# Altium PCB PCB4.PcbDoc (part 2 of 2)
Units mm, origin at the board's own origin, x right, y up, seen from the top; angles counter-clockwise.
Board outline 70 x 70 mm, 2 copper layers (Top Layer, Bottom Layer); 41 components, 63 nets, 218 pads, 36 vias.
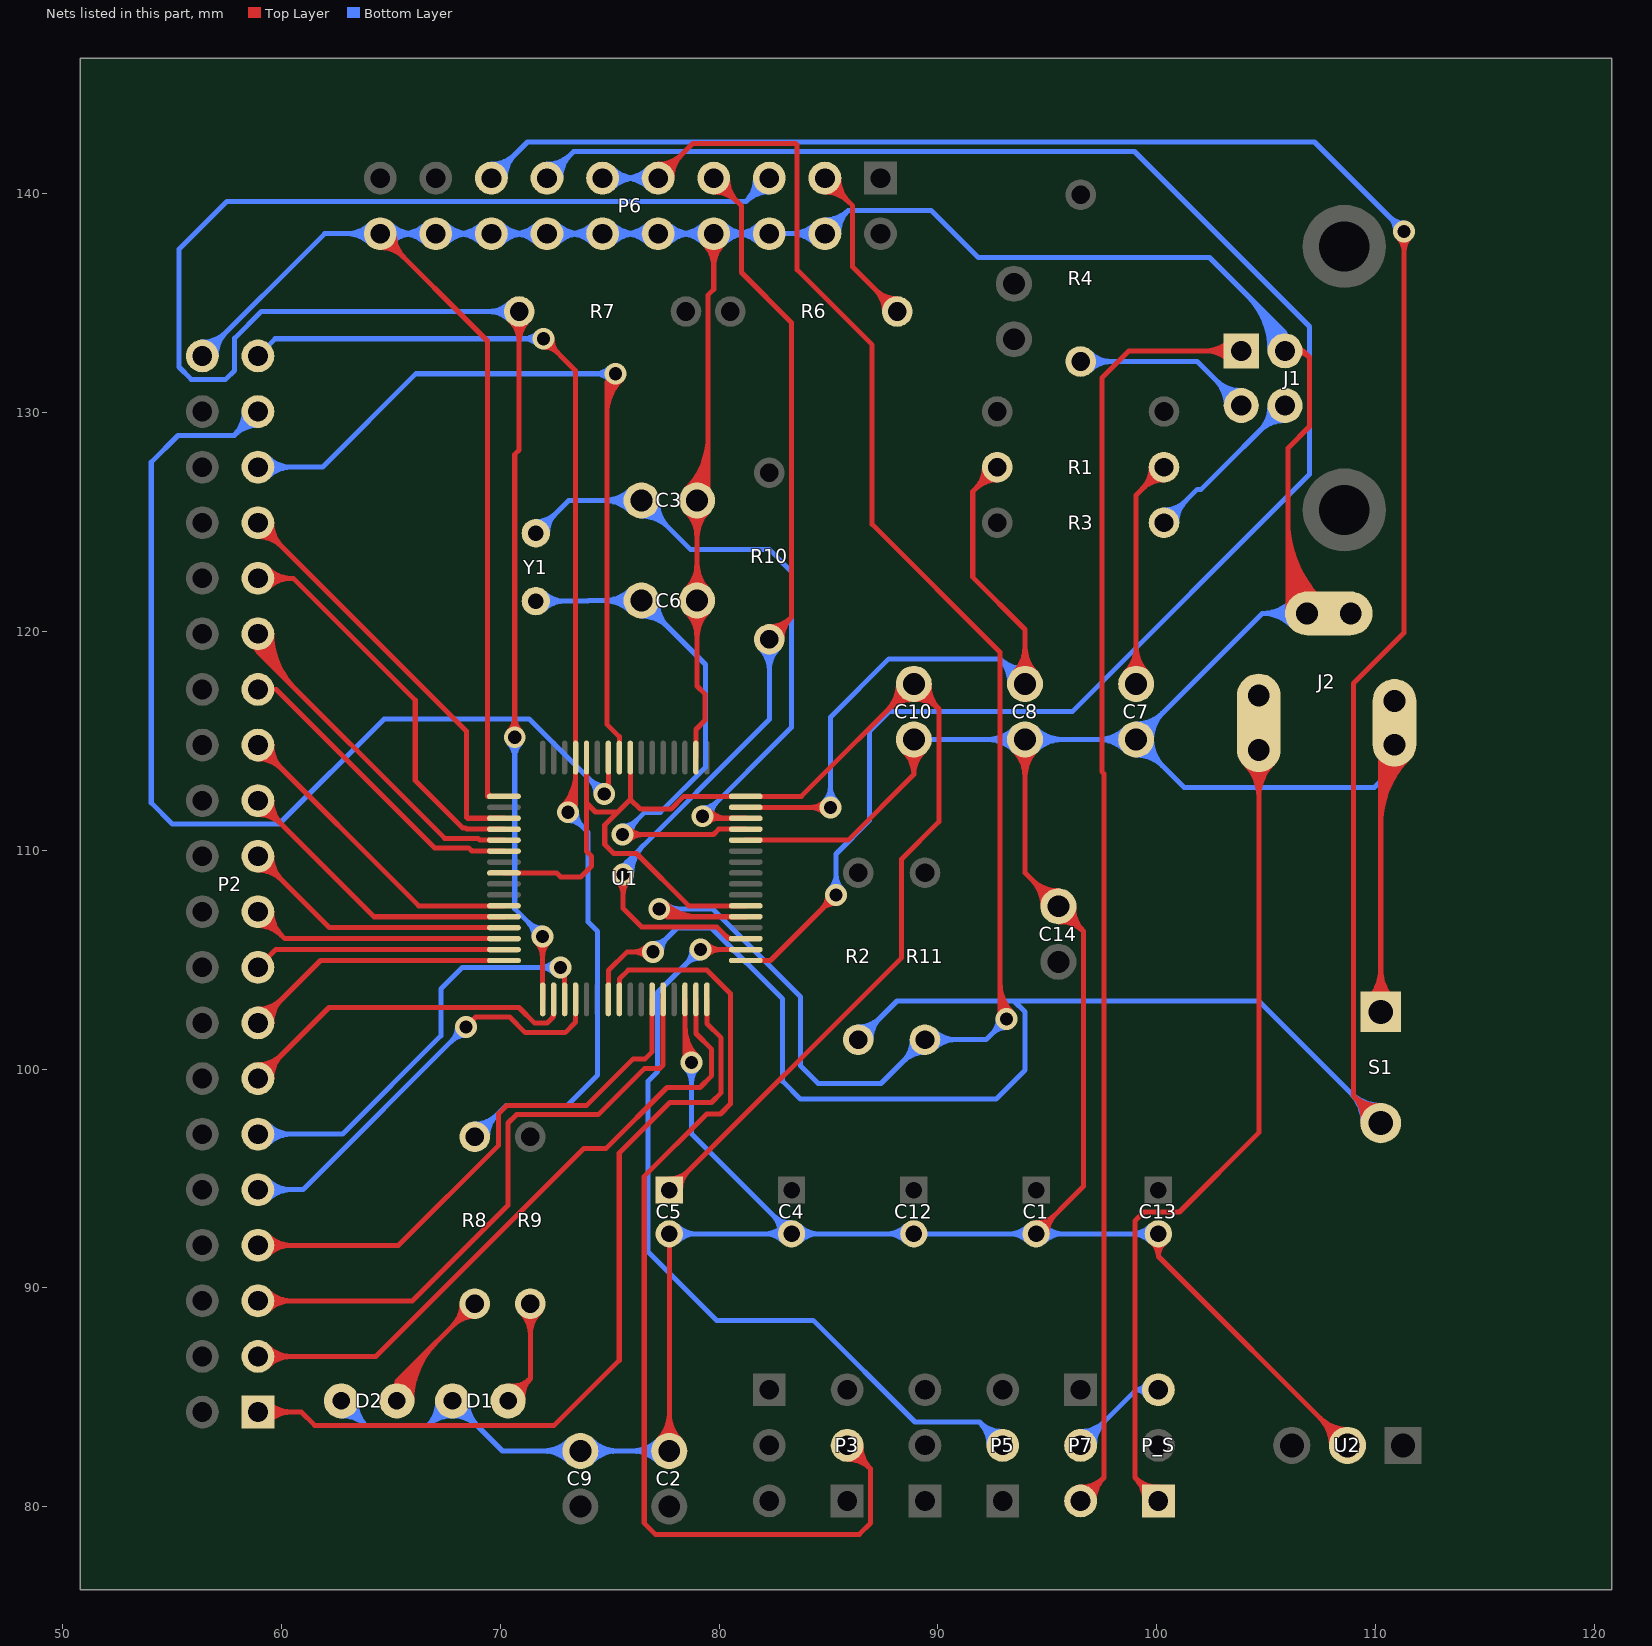
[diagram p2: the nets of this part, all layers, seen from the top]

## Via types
v1: diameter 1, hole 0.6, Top Layer to Bottom Layer, 36 vias

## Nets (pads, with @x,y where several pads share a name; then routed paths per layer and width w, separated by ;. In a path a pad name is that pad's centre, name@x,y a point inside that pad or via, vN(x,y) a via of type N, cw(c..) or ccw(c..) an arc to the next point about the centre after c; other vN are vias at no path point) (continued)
GND: C1.2 C2.1 C3.2 C4.2 C5.2 C6.2 C7.2 C8.2 C9.1 C10.1 C12.2 C13.2 C14.1 D1.2 D2.2 J1.4 J2.2 J2.2A J2.2B J2.3 J2.3A J2.3B P2.40 P6.4 P6.6 P6.8 P6.10 P6.12 P6.14 P6.16 P6.18 P6.20 S1.1 U1.2 U1.17 U1.46 U1.60 U2.2 | length 565.4
  Top Layer w0.23: P6.20@64.516,137.541 cw(c64.516,136.008) 65.6,137.092 cw(c66.684,138.176) P6.20@65.151,138.176 ; P6.20@64.516,137.771 cw(c64.516,136.793) 65.207,137.485 cw(c65.899,138.176) P6.20@64.921,138.176 ; P6.20@64.516,138.176 69.418,133.274 69.418,112.462 U1.17@70.167,112.462 ; 69.418,112.726 ccw(c69.781,112.726) U1.17@69.524,112.469 ; C2.1@77.222,83.052 ccw(c76.01,84.264) 77.724,84.264 ccw(c79.438,84.264) C2.1@78.226,83.052 ; C2.1@77.385,82.889 ccw(c76.565,83.709) 77.724,83.709 ccw(c78.883,83.709) C2.1@78.063,82.889 ; C2.1@77.724,82.55 C5.2@77.724,92.472 ; 78.442,100.843 ccw(c79.278,100.843) v1@78.687,100.252 ; 78.442,101.398 ccw(c79.834,101.398) v1@78.85,100.414 ; 78.442,101.953 ccw(c80.389,101.953) v1@79.012,100.577 ; U1.46@78.442,103.187 78.442,100.603 v1(78.74,100.305) ; C6.2@78.492,120.91 cw(c77.28,119.698) 78.994,119.698 cw(c80.708,119.698) C6.2@79.496,120.91 ; C6.2@78.492,121.914 ccw(c77.28,123.126) 78.994,123.126 ccw(c80.708,123.126) C6.2@79.496,121.914 ; C3.2@78.492,125.482 cw(c77.28,124.27) 78.994,124.27 cw(c80.708,124.27) C3.2@79.496,125.482 ; C3.2@78.492,126.486 ccw(c76.053,128.925) 79.502,128.925 ; C6.2@78.655,121.073 cw(c77.835,120.253) 78.994,120.253 cw(c80.153,120.253) C6.2@79.333,121.073 ; C6.2@78.655,121.751 ccw(c77.835,122.571) 78.994,122.571 ccw(c80.153,122.571) C6.2@79.333,121.751 ; C3.2@78.655,125.645 cw(c77.835,124.825) 78.994,124.825 cw(c80.153,124.825) C3.2@79.333,125.645 ; C3.2@78.655,126.323 ccw(c76.609,128.369) 79.502,128.369 ; C3.2@78.817,126.161 ccw(c77.164,127.814) 79.502,127.814 ; U1.2@78.942,114.237 78.942,115.517 79.352,115.927 79.352,117.147 78.994,117.505 C6.2@78.994,121.412 C3.2@78.994,125.984 79.502,125.984 79.502,135.382 79.756,135.636 P6.8@79.756,138.176 ; C3.2@78.98,125.998 ccw(c77.719,127.259) 79.502,127.259 ; C3.2@79.142,125.836 ccw(c78.275,126.703) 79.502,126.703 ; P6.8@79.307,137.727 cw(c78.223,136.643) 79.756,136.643 cw(c81.289,136.643) P6.8@80.205,137.727 ; P6.8@79.47,137.89 cw(c78.778,137.198) 79.756,137.198 cw(c80.734,137.198) P6.8@80.042,137.89 ; U1.60@81.217,110.462 85.9,110.462 88.9,113.462 ; C10.1@88.424,114.536 cw(c87.452,113.462) 88.9,113.462 ; C10.1@88.578,114.706 cw(c87.921,113.98) 88.9,113.98 cw(c89.879,113.98) C10.1@89.222,114.706 ; C10.1@88.9,115.062 88.9,113.462 ; C10.1@89.376,114.536 ccw(c90.348,113.462) 88.9,113.462 ; C8.2@93.478,114.56 cw(c92.266,113.348) 93.98,113.348 cw(c95.694,113.348) C8.2@94.482,114.56 ; C8.2@93.641,114.723 cw(c92.821,113.903) 93.98,113.903 cw(c95.139,113.903) C8.2@94.319,114.723 ; C8.2@93.98,115.062 93.98,108.966 C14.1@95.504,107.442 96.647,106.299 ; C1.2@94.488,92.472 96.647,94.631 96.647,106.299 ; C1.2@94.488,92.752 ccw(c94.488,93.428) 94.966,92.95 ccw(c95.444,92.472) C1.2@94.768,92.472 ; C1.2@94.488,92.982 ccw(c94.488,94.213) 95.359,93.343 ccw(c96.229,92.472) C1.2@94.998,92.472 ; C14.1@94.794,107.442 ccw(c93.08,107.442) 94.292,108.654 ccw(c95.504,109.866) C14.1@95.504,108.152 ; C14.1@95.024,107.442 ccw(c93.865,107.442) 94.685,108.261 ccw(c95.504,109.081) C14.1@95.504,107.922 ; C14.1@95.524,106.962 cw(c95.567,105.959) 96.277,106.669 cw(c96.987,107.379) C14.1@95.984,107.422 ; C14.1@95.534,106.733 cw(c95.597,105.249) 96.647,106.299 ; C14.1@96.213,107.412 ccw(c97.697,107.349) 96.647,106.299 ; C13.2@99.766,92.067 cw(c99.287,91.44) 100.076,91.44 ; C13.2@100.076,92.472 100.076,91.44 ; C13.2@100.386,92.067 ccw(c100.865,91.44) 100.076,91.44 ; J1.4@105.859,132.826 cw(c106.254,132.195) 106.781,132.721 ; J1.4@105.862,132.822 106.68,132.822 106.985,132.517 ; J1.4@105.981,132.631 cw(c106.411,131.943) 106.985,132.517 ; 105.994,121.729 ccw(c107.769,121.729) J2.3@106.514,120.474 ; 105.994,122.284 ccw(c108.324,122.284) J2.3@106.677,120.637 ; 105.994,122.839 ccw(c108.879,122.839) J2.3@106.839,120.799 ; 105.994,123.395 ccw(c109.435,123.395) J2.3@107.002,120.962 ; 105.994,123.95 ccw(c109.99,123.95) J2.3@107.165,121.125 ; 105.994,124.505 ccw(c110.545,124.505) J2.3@107.327,121.287 ; 105.994,125.06 ccw(c111.1,125.06) J2.3@107.49,121.45 ; J2.3@106.259,120.631 ccw(c105.994,120.546) J2.3@105.994,120.824 ; J2.3@106.259,121.017 cw(c105.994,121.102) J2.3@105.994,120.824 ; J2.3@107.439,120.554 cw(c107.864,120.354) J2.3@107.864,120.824 ; J2.3@107.439,121.094 ccw(c107.864,121.294) J2.3@107.864,120.824 ; U2.2@107.977,82.804 ccw(c106.203,82.804) 107.457,84.059 ccw(c108.712,85.313) U2.2@108.712,83.539 ; U2.2@108.207,82.804 ccw(c106.988,82.804) 107.85,83.666 ccw(c108.712,84.528) U2.2@108.712,83.309 ; U2.2@108.712,82.804 100.076,91.44 ; S1.1@109.663,103.189 ccw(c108.28,104.572) 110.236,104.572 ccw(c112.192,104.572) S1.1@110.809,103.189 ; S1.1@109.826,103.026 ccw(c108.836,104.016) 110.236,104.016 ccw(c111.636,104.016) S1.1@110.646,103.026 ; S1.1@110.236,102.616 110.236,114.196 J2.2B@110.864,114.824 J2.2@110.864,115.824 ; 110.236,111.171 cw(c114.517,111.171) J2.2@111.49,114.198 ; 110.236,111.727 cw(c113.961,111.727) J2.2@111.327,114.361 ; 110.236,112.282 cw(c113.406,112.282) J2.2@111.165,114.523 ; 110.236,112.837 cw(c112.851,112.837) J2.2@111.002,114.686 ; 110.236,113.392 cw(c112.296,113.392) J2.2@110.839,114.849 ; 110.236,113.948 cw(c111.74,113.948) J2.2@110.677,115.011 ; J2.2@110.594,115.399 ccw(c110.394,115.824) J2.2@110.864,115.824 ; J2.2@110.594,116.249 cw(c110.394,115.824) J2.2@110.864,115.824 ; J2.2A@110.864,116.824 J2.2@110.864,115.824 ; J2.2@111.134,115.399 cw(c111.334,115.824) J2.2@110.864,115.824 ; J2.2@111.134,116.249 ccw(c111.334,115.824) J2.2@110.864,115.824 ; J2.3@105.994,120.824 J2.3B@106.864,120.824 J2.3@107.864,120.824 ; J2.3@105.994,120.824 105.994,128.372 106.985,129.362 106.985,132.517
  Bottom Layer w0.23: P2.40@56.388,132.588 61.976,138.176 P6.20@64.516,138.176 P6.18@67.056,138.176 P6.16@69.596,138.176 P6.14@72.136,138.176 P6.12@74.676,138.176 P6.10@77.216,138.176 P6.8@79.756,138.176 P6.6@82.296,138.176 P6.4@84.836,138.176 85.903,139.243 ; P2.40@56.388,132.993 ccw(c56.388,133.971) 57.079,133.279 ccw(c57.771,132.588) P2.40@56.793,132.588 ; P2.40@56.388,133.223 ccw(c56.388,134.756) 57.472,133.672 ccw(c58.556,132.588) P2.40@57.023,132.588 ; D2.2@62.738,84.836 63.856,83.718 ; D2.2@62.753,84.381 cw(c62.785,83.398) 63.48,84.094 cw(c64.176,84.789) D2.2@63.193,84.821 ; D2.2@62.76,84.151 cw(c62.809,82.671) 63.856,83.718 ; D2.2@63.423,84.814 ccw(c64.903,84.765) 63.856,83.718 ; P6.20@64.067,137.727 ccw(c62.983,136.643) 62.983,138.176 ccw(c62.983,139.709) P6.20@64.067,138.625 ; P6.20@64.23,137.89 ccw(c63.538,137.198) 63.538,138.176 ccw(c63.538,139.154) P6.20@64.23,138.462 ; P6.20@64.802,137.89 cw(c65.494,137.198) 65.494,138.176 cw(c65.494,139.154) P6.20@64.802,138.462 ; P6.20@64.965,137.727 cw(c66.049,136.643) 66.049,138.176 cw(c66.049,139.709) P6.20@64.965,138.625 ; P6.18@66.607,137.727 ccw(c65.523,136.643) 65.523,138.176 ccw(c65.523,139.709) P6.18@66.607,138.625 ; P6.18@66.77,137.89 ccw(c66.078,137.198) 66.078,138.176 ccw(c66.078,139.154) P6.18@66.77,138.462 ; D1.2@67.133,84.814 cw(c65.653,84.765) 66.7,83.718 ; P6.18@67.342,137.89 cw(c68.034,137.198) 68.034,138.176 cw(c68.034,139.154) P6.18@67.342,138.462 ; D1.2@67.363,84.821 cw(c66.38,84.789) 67.076,84.094 cw(c67.771,83.398) D1.2@67.803,84.381 ; P6.18@67.505,137.727 cw(c68.589,136.643) 68.589,138.176 cw(c68.589,139.709) P6.18@67.505,138.625 ; D1.2@67.796,84.151 ccw(c67.747,82.671) 66.7,83.718 ; D1.2@67.818,84.151 cw(c67.818,82.497) 68.987,83.667 cw(c70.157,84.836) D1.2@68.503,84.836 ; D1.2@67.818,84.381 cw(c67.818,83.283) 68.595,84.059 cw(c69.371,84.836) D1.2@68.273,84.836 ; P6.16@69.147,137.727 ccw(c68.063,136.643) 68.063,138.176 ccw(c68.063,139.709) P6.16@69.147,138.625 ; P6.16@69.31,137.89 ccw(c68.618,137.198) 68.618,138.176 ccw(c68.618,139.154) P6.16@69.31,138.462 ; P6.16@69.882,137.89 cw(c70.574,137.198) 70.574,138.176 cw(c70.574,139.154) P6.16@69.882,138.462 ; P6.16@70.045,137.727 cw(c71.129,136.643) 71.129,138.176 cw(c71.129,139.709) P6.16@70.045,138.625 ; P6.14@71.687,137.727 ccw(c70.603,136.643) 70.603,138.176 ccw(c70.603,139.709) P6.14@71.687,138.625 ; P6.14@71.85,137.89 ccw(c71.158,137.198) 71.158,138.176 ccw(c71.158,139.154) P6.14@71.85,138.462 ; P6.14@72.422,137.89 cw(c73.114,137.198) 73.114,138.176 cw(c73.114,139.154) P6.14@72.422,138.462 ; P6.14@72.585,137.727 cw(c73.669,136.643) 73.669,138.176 cw(c73.669,139.709) P6.14@72.585,138.625 ; C9.1@73.158,82.048 ccw(c71.946,80.836) 71.946,82.55 ccw(c71.946,84.264) C9.1@73.158,83.052 ; C9.1@73.321,82.211 ccw(c72.501,81.391) 72.501,82.55 ccw(c72.501,83.709) C9.1@73.321,82.889 ; C9.1@73.999,82.211 cw(c74.819,81.391) 74.819,82.55 cw(c74.819,83.709) C9.1@73.999,82.889 ; C9.1@74.162,82.048 cw(c75.374,80.836) 75.374,82.55 cw(c75.374,84.264) C9.1@74.162,83.052 ; P6.12@74.227,137.727 ccw(c73.143,136.643) 73.143,138.176 ccw(c73.143,139.709) P6.12@74.227,138.625 ; P6.12@74.39,137.89 ccw(c73.698,137.198) 73.698,138.176 ccw(c73.698,139.154) P6.12@74.39,138.462 ; P6.12@74.962,137.89 cw(c75.654,137.198) 75.654,138.176 cw(c75.654,139.154) P6.12@74.962,138.462 ; P6.12@75.125,137.727 cw(c76.209,136.643) 76.209,138.176 cw(c76.209,139.709) P6.12@75.125,138.625 ; P6.10@76.767,137.727 ccw(c75.683,136.643) 75.683,138.176 ccw(c75.683,139.709) P6.10@76.767,138.625 ; P6.10@76.93,137.89 ccw(c76.238,137.198) 76.238,138.176 ccw(c76.238,139.154) P6.10@76.93,138.462 ; C2.1@77.222,82.048 ccw(c76.01,80.836) 76.01,82.55 ccw(c76.01,84.264) C2.1@77.222,83.052 ; C2.1@77.385,82.211 ccw(c76.565,81.391) 76.565,82.55 ccw(c76.565,83.709) C2.1@77.385,82.889 ; P6.10@77.502,137.89 cw(c78.194,137.198) 78.194,138.176 cw(c78.194,139.154) P6.10@77.502,138.462 ; P6.10@77.665,137.727 cw(c78.749,136.643) 78.749,138.176 cw(c78.749,139.709) P6.10@77.665,138.625 ; C2.1@77.724,82.55 C9.1@73.66,82.55 70.104,82.55 D1.2@67.818,84.836 66.7,83.718 ; C5.2@77.724,92.472 C4.2@83.312,92.472 ; C5.2@77.922,92.274 cw(c78.4,91.796) 78.4,92.472 cw(c78.4,93.148) C5.2@77.922,92.67 ; C5.2@78.085,92.111 cw(c78.955,91.241) 78.955,92.472 cw(c78.955,93.703) C5.2@78.085,92.833 ; v1@78.468,100.032 cw(c77.811,99.375) 78.74,99.375 cw(c79.669,99.375) v1@79.012,100.032 ; v1(78.74,100.305) 78.74,97.044 C4.2@83.312,92.472 ; P6.8@79.307,137.727 ccw(c78.223,136.643) 78.223,138.176 ccw(c78.223,139.709) P6.8@79.307,138.625 ; P6.8@79.47,137.89 ccw(c78.778,137.198) 78.778,138.176 ccw(c78.778,139.154) P6.8@79.47,138.462 ; P6.8@80.042,137.89 cw(c80.734,137.198) 80.734,138.176 cw(c80.734,139.154) P6.8@80.042,138.462 ; P6.8@80.205,137.727 cw(c81.289,136.643) 81.289,138.176 cw(c81.289,139.709) P6.8@80.205,138.625 ; P6.6@81.847,137.727 ccw(c80.763,136.643) 80.763,138.176 ccw(c80.763,139.709) P6.6@81.847,138.625 ; P6.6@82.01,137.89 ccw(c81.318,137.198) 81.318,138.176 ccw(c81.318,139.154) P6.6@82.01,138.462 ; C4.2@82.802,92.472 ccw(c81.571,92.472) 82.441,93.343 ccw(c83.312,94.213) C4.2@83.312,92.982 ; C4.2@82.951,92.111 ccw(c82.081,91.241) 82.081,92.472 ccw(c82.081,93.703) C4.2@82.951,92.833 ; C4.2@83.032,92.472 ccw(c82.356,92.472) 82.834,92.95 ccw(c83.312,93.428) C4.2@83.312,92.752 ; C4.2@83.114,92.274 ccw(c82.636,91.796) 82.636,92.472 ccw(c82.636,93.148) C4.2@83.114,92.67 ; C4.2@83.51,92.274 cw(c83.988,91.796) 83.988,92.472 cw(c83.988,93.148) C4.2@83.51,92.67 ; C4.2@83.673,92.111 cw(c84.543,91.241) 84.543,92.472 cw(c84.543,93.703) C4.2@83.673,92.833 ; P6.4@84.387,137.727 ccw(c83.303,136.643) 83.303,138.176 ccw(c83.303,139.709) P6.4@84.387,138.625 ; P6.4@84.55,137.89 ccw(c83.858,137.198) 83.858,138.176 ccw(c83.858,139.154) P6.4@84.55,138.462 ; P6.4@84.841,138.581 ccw(c84.851,139.521) 85.516,138.856 ccw(c86.181,138.191) P6.4@85.241,138.181 ; P6.4@84.843,138.811 ccw(c84.86,140.285) 85.903,139.243 ; P6.4@85.471,138.183 cw(c86.945,138.2) 85.903,139.243 ; C12.2@88.539,92.111 ccw(c87.669,91.241) 87.669,92.472 ccw(c87.669,93.703) C12.2@88.539,92.833 ; C12.2@88.702,92.274 ccw(c88.224,91.796) 88.224,92.472 ccw(c88.224,93.148) C12.2@88.702,92.67 ; C10.1@88.9,115.062 C8.2@93.98,115.062 C7.2@99.06,115.062 ; C8.2@93.478,114.56 ccw(c92.266,113.348) 92.266,115.062 ccw(c92.266,116.776) C8.2@93.478,115.564 ; C8.2@93.641,114.723 ccw(c92.821,113.903) 92.821,115.062 ccw(c92.821,116.221) C8.2@93.641,115.401 ; C1.2@94.127,92.111 ccw(c93.257,91.241) 93.257,92.472 ccw(c93.257,93.703) C1.2@94.127,92.833 ; C1.2@94.29,92.274 ccw(c93.812,91.796) 93.812,92.472 ccw(c93.812,93.148) C1.2@94.29,92.67 ; C8.2@94.319,114.723 cw(c95.139,113.903) 95.139,115.062 cw(c95.139,116.221) C8.2@94.319,115.401 ; C8.2@94.482,114.56 cw(c95.694,113.348) 95.694,115.062 cw(c95.694,116.776) C8.2@94.482,115.564 ; C1.2@94.686,92.274 cw(c95.164,91.796) 95.164,92.472 cw(c95.164,93.148) C1.2@94.686,92.67 ; C1.2@94.849,92.111 cw(c95.719,91.241) 95.719,92.472 cw(c95.719,93.703) C1.2@94.849,92.833 ; C7.2@98.558,114.56 ccw(c97.346,113.348) 97.346,115.062 ccw(c97.346,116.776) C7.2@98.558,115.564 ; C7.2@98.721,114.723 ccw(c97.901,113.903) 97.901,115.062 ccw(c97.901,116.221) C7.2@98.721,115.401 ; C7.2@99.06,114.352 cw(c99.06,112.638) 100.272,113.85 cw(c101.484,115.062) 99.77,115.062 cw(c101.484,115.062) 100.272,116.274 cw(c99.06,117.486) C7.2@99.06,115.772 ; C7.2@99.06,114.582 cw(c99.06,113.423) 99.879,114.243 cw(c100.699,115.062) 99.54,115.062 cw(c100.699,115.062) 99.879,115.881 cw(c99.06,116.701) C7.2@99.06,115.542 ; C13.2@99.715,92.111 ccw(c98.845,91.241) 98.845,92.472 ccw(c98.845,93.703) C13.2@99.715,92.833 ; C13.2@99.878,92.274 ccw(c99.4,91.796) 99.4,92.472 ccw(c99.4,93.148) C13.2@99.878,92.67 ; C13.2@100.076,92.472 C1.2@94.488,92.472 C12.2@88.9,92.472 C4.2@83.312,92.472 ; 104.118,135.379 cw(c101.562,132.822) J1.4@105.177,132.822 ; 104.511,134.986 cw(c102.347,132.822) J1.4@105.407,132.822 ; 104.903,134.593 cw(c103.132,132.822) J1.4@105.637,132.822 ; 105.296,134.201 cw(c103.917,132.822) J1.4@105.867,132.822 ; 105.689,133.808 cw(c104.703,132.822) J1.4@106.097,132.822 ; J1.4@105.862,132.822 105.862,133.635 102.413,137.084 91.846,137.084 89.687,139.243 85.903,139.243 ; J2.3@106.218,120.219 ccw(c104.822,118.911) 104.822,120.824 ; J2.3@106.218,121.429 cw(c104.822,122.737) 104.822,120.824 ; J2.3@106.386,120.376 ccw(c105.353,119.408) 105.353,120.824 ccw(c105.353,122.24) J2.3@106.386,121.272 ; J2.3@106.415,120.375 ccw(c105.331,119.291) 105.331,120.824 ccw(c105.331,122.357) J2.3@106.415,121.273 ; J2.3@106.578,120.538 ccw(c105.886,119.846) 105.886,120.824 ccw(c105.886,121.802) J2.3@106.578,121.11 ; J2.3@108.289,120.554 ccw(c107.864,120.354) J2.3@107.864,120.824 ; J2.3@108.289,121.094 cw(c107.864,121.294) J2.3@107.864,120.824 ; J2.3A@108.864,120.824 J2.3@107.864,120.824 ; J2.2@110.578,114.257 cw(c110.343,113.792) 110.864,113.792 ; J2.2@110.594,115.399 ccw(c110.394,115.824) J2.2@110.864,115.824 ; J2.2@111.134,115.399 cw(c111.334,115.824) J2.2@110.864,115.824 ; J2.2@111.15,114.257 ccw(c111.385,113.792) 110.864,113.792 ; 63.856,83.718 66.7,83.718 ; C7.2@99.06,115.062 101.244,112.878 109.95,112.878 110.864,113.792 ; C7.2@99.06,115.062 104.822,120.824 ; 104.822,120.824 J2.3B@106.864,120.824 ; J2.3B@106.864,120.824 J2.3@107.864,120.824 ; J2.3B@106.864,120.824 J2.3@107.864,120.824 ; J2.3@107.864,120.824 cw(c107.864,121.294) 107.439,121.094 ccw(c107.864,121.294) J2.3@107.864,120.824 ; J2.3@107.864,120.824 ccw(c107.864,120.354) 107.439,120.554 cw(c107.864,120.354) J2.3@107.864,120.824 ; 110.864,113.792 J2.2B@110.864,114.824 J2.2@110.864,115.824
JTAGSEL: P5.2 U1.50 | length 43.5
  Top Layer w0.23: v1(79.148,105.462) U1.50@81.217,105.462 ; v1@79.42,105.19 cw(c80.077,104.533) 80.077,105.462 cw(c80.077,106.391) v1@79.42,105.734
  Bottom Layer w0.23: v1@78.763,105.462 cw(c77.833,105.462) 78.49,104.805 cw(c79.148,104.148) v1@79.148,105.077 ; v1(79.148,105.462) 77.189,103.503 77.189,99.884 76.759,99.454 76.759,91.643 79.883,88.519 84.303,88.519 88.951,83.871 91.897,83.871 ; P5.2@92.329,82.811 ccw(c90.855,82.828) 91.897,83.871 ; P5.2@92.559,82.809 ccw(c91.619,82.819) 92.284,83.484 ccw(c92.949,84.149) P5.2@92.959,83.209 ; P5.2@92.957,83.439 cw(c92.94,84.913) 91.897,83.871 ; P5.2@92.964,82.804 91.897,83.871
NetC7_1: C7.1 R1.2 | length 18.5
  Top Layer w0.23: C7.1@98.558,118.104 ccw(c97.346,119.316) 99.06,119.316 ccw(c100.774,119.316) C7.1@99.562,118.104 ; C7.1@98.721,117.941 ccw(c97.901,118.761) 99.06,118.761 ccw(c100.219,118.761) C7.1@99.399,117.941 ; C7.1@99.06,117.602 99.06,126.238 R1.2@100.33,127.508 ; R1.2@99.745,127.508 cw(c98.333,127.508) 99.331,126.509 cw(c100.33,125.511) R1.2@100.33,126.923 ; R1.2@99.975,127.508 cw(c99.118,127.508) 99.724,126.902 cw(c100.33,126.296) R1.2@100.33,127.153
NetD1_1: D1.1 R9.2 | length 11.9
  Top Layer w0.23: D1.1@70.358,84.836 71.374,85.852 ; D1.1@70.405,85.289 ccw(c70.486,86.058) 71.033,85.511 ccw(c71.58,84.964) D1.1@70.811,84.883 ; D1.1@70.429,85.517 ccw(c70.551,86.675) 71.374,85.852 ; R9.2@70.96,88.867 cw(c69.962,87.869) 71.374,87.869 cw(c72.786,87.869) R9.2@71.788,88.867 ; D1.1@71.039,84.907 cw(c72.197,85.029) 71.374,85.852 ; R9.2@71.123,89.03 cw(c70.517,88.424) 71.374,88.424 cw(c72.231,88.424) R9.2@71.625,89.03 ; R9.2@71.374,89.281 71.374,85.852
NetD2_1: D2.1 R8.1 | length 20
  Top Layer w0.23: D2.1@65.043,84.836 cw(c66.622,84.836) 65.505,85.952 ; D2.1@65.273,84.836 cw(c67.407,84.836) 65.898,86.345 ; D2.1@65.278,84.836 65.278,85.725 R8.1@68.834,89.281 ; D2.1@65.503,84.836 cw(c68.192,84.836) 66.291,86.738 ; D2.1@65.733,84.836 cw(c68.978,84.836) 66.683,87.13 ; D2.1@65.963,84.836 cw(c69.763,84.836) 67.076,87.523 ; R8.1@68.249,89.281 cw(c66.837,89.281) 67.835,88.282 cw(c68.834,87.284) R8.1@68.834,88.696 ; R8.1@68.479,89.281 cw(c67.622,89.281) 68.228,88.675 cw(c68.834,88.069) R8.1@68.834,88.926
NetJ1_1: J1.1 P7.3 | length 66.9
  Top Layer w0.23: P7.3@96.52,80.264 97.587,81.331 ; P7.3@96.525,80.669 ccw(c96.535,81.609) 97.2,80.944 ccw(c97.865,80.279) P7.3@96.925,80.269 ; P7.3@96.527,80.899 ccw(c96.544,82.373) 97.587,81.331 ; P7.3@97.155,80.271 cw(c98.629,80.288) 97.587,81.331 ; J1.1@103.378,132.338 ccw(c102.208,131.168) 102.208,132.822 ccw(c102.208,134.476) J1.1@103.378,133.306 ; J1.1@103.54,132.5 ccw(c102.764,131.724) 102.764,132.822 ccw(c102.764,133.92) J1.1@103.54,133.144 ; J1.1@103.862,132.822 98.735,132.822 97.49,131.577 97.49,113.589 97.587,113.492 97.587,81.331
NetJ1_2: J1.2 R4.1 | length 16.1
  Bottom Layer w0.23: R4.1@96.52,132.334 101.85,132.334 J1.2@103.862,130.322 ; R4.1@96.771,132.083 cw(c97.377,131.477) 97.377,132.334 cw(c97.377,133.191) R4.1@96.771,132.585 ; R4.1@96.934,131.92 cw(c97.932,130.922) 97.932,132.334 cw(c97.932,133.746) R4.1@96.934,132.748 ; J1.2@103.177,130.322 ccw(c101.523,130.322) 102.693,131.491 ccw(c103.862,132.661) J1.2@103.862,131.007 ; J1.2@103.407,130.322 ccw(c102.309,130.322) 103.085,131.099 ccw(c103.862,131.875) J1.2@103.862,130.777
NetJ1_3: J1.3 R3.1 | length 15.6
  Bottom Layer w0.23: R3.1@100.33,124.968 101.854,126.492 102.032,126.492 J1.3@105.862,130.322 ; R3.1@100.33,125.323 ccw(c100.33,126.18) 100.936,125.574 ccw(c101.542,124.968) R3.1@100.685,124.968 ; R3.1@100.33,125.553 ccw(c100.33,126.965) 101.329,125.967 ccw(c102.327,124.968) R3.1@100.915,124.968 ; J1.3@105.177,130.322 cw(c103.523,130.322) 104.693,129.153 cw(c105.862,127.983) J1.3@105.862,129.637 ; J1.3@105.407,130.322 cw(c104.309,130.322) 105.085,129.545 cw(c105.862,128.769) J1.3@105.862,129.867
NetJ2_1: J2.1 J2.1A J2.1B P_S.1 | length 65.5
  Top Layer w0.23: P_S.1@99.441,80.271 ccw(c97.967,80.288) 99.009,81.331 ; P_S.1@99.671,80.269 ccw(c98.731,80.279) 99.396,80.944 ccw(c100.061,81.609) P_S.1@100.071,80.669 ; P_S.1@100.069,80.899 cw(c100.052,82.373) 99.009,81.331 ; P_S.1@100.076,80.264 99.009,81.331 ; J2.1@104.038,113.948 cw(c102.527,112.437) 104.664,112.437 cw(c106.801,112.437) J2.1@105.29,113.948 ; J2.1@104.201,114.111 cw(c103.083,112.993) 104.664,112.993 cw(c106.245,112.993) J2.1@105.127,114.111 ; J2.1@104.215,114.125 cw(c103.131,113.041) 104.664,113.041 cw(c106.197,113.041) J2.1@105.113,114.125 ; J2.1@104.29,116.561 cw(c103.751,115.824) J2.1@104.664,115.824 ; J2.1@104.363,114.273 cw(c103.638,113.548) 104.664,113.548 cw(c105.69,113.548) J2.1@104.965,114.273 ; J2.1@104.378,114.288 cw(c103.686,113.596) 104.664,113.596 cw(c105.642,113.596) J2.1@104.95,114.288 ; J2.1@104.425,116.747 cw(c104.082,116.277) 104.664,116.277 cw(c105.246,116.277) J2.1@104.903,116.747 ; J2.1A@104.664,117.074 J2.1@104.664,115.824 ; J2.1@105.038,116.561 ccw(c105.577,115.824) J2.1@104.664,115.824 ; 99.009,81.331 99.009,93.066 99.416,93.472 101.041,93.472 104.664,97.095 J2.1B@104.664,114.574 ; J2.1B@104.664,114.574 J2.1@104.664,115.824 ; J2.1B@104.664,114.574 J2.1@104.664,115.824 ; J2.1@104.664,115.371 cw(c104.082,115.371) 104.425,114.901 ccw(c104.082,115.371) J2.1@104.664,115.371 ; J2.1@104.664,115.371 ccw(c105.246,115.371) 104.903,114.901 cw(c105.246,115.371) J2.1@104.664,115.371 ; J2.1@104.664,115.824 cw(c103.751,115.824) 104.29,115.087 ccw(c103.751,115.824) J2.1@104.664,115.824 ; J2.1@104.664,115.824 ccw(c105.577,115.824) 105.038,115.087 cw(c105.577,115.824) J2.1@104.664,115.824
NetP2_1: P2.1 U1.48 | length 41.7
  Top Layer w0.23: P2.1@58.928,84.328 60.909,84.328 61.519,83.718 72.466,83.718 75.438,86.69 75.438,96.164 77.749,98.476 79.654,98.476 80.093,98.915 80.093,101.431 79.442,102.083 U1.48@79.442,103.187 ; P2.1@59.214,84.042 cw(c59.906,83.35) 59.906,84.328 cw(c59.906,85.306) P2.1@59.214,84.614 ; P2.1@59.377,83.879 cw(c60.461,82.795) 60.461,84.328 cw(c60.461,85.861) P2.1@59.377,84.777
NetP2_3: P2.3 U1.47 | length 33.8
  Top Layer w0.23: P2.3@58.928,86.868 64.315,86.868 73.825,96.378 74.838,96.378 77.621,99.161 79.125,99.161 79.663,99.7 79.663,100.903 78.942,101.625 U1.47@78.942,103.187 ; P2.3@59.214,86.582 cw(c59.906,85.89) 59.906,86.868 cw(c59.906,87.846) P2.3@59.214,87.154 ; P2.3@59.377,86.419 cw(c60.461,85.335) 60.461,86.868 cw(c60.461,88.401) P2.3@59.377,87.317
NetP2_5: P2.5 U1.44 | length 32.1
  Top Layer w0.23: P2.5@58.928,89.408 65.989,89.408 70.358,93.777 70.358,97.535 70.739,97.916 74.477,97.916 76.598,100.037 77.298,100.037 77.442,100.181 U1.44@77.442,103.187 ; P2.5@59.214,89.122 cw(c59.906,88.43) 59.906,89.408 cw(c59.906,90.386) P2.5@59.214,89.694 ; P2.5@59.377,88.959 cw(c60.461,87.875) 60.461,89.408 cw(c60.461,90.941) P2.5@59.377,89.857
NetP2_7: P2.7 U1.43 | length 28.9
  Top Layer w0.23: P2.7@58.928,91.948 65.354,91.948 69.926,96.52 69.926,97.965 70.307,98.346 73.951,98.346 76.072,100.467 76.622,100.467 76.942,100.787 U1.43@76.942,103.187 ; P2.7@59.214,91.662 cw(c59.906,90.97) 59.906,91.948 cw(c59.906,92.926) P2.7@59.214,92.234 ; P2.7@59.377,91.499 cw(c60.461,90.415) 60.461,91.948 cw(c60.461,93.481) P2.7@59.377,92.397
NetP2_9: P2.9 U1.36 | length 24.7
  Top Layer w0.23: v1(68.428,101.93) 68.88,102.383 70.428,102.383 71.144,101.667 72.965,101.667 73.442,102.144 U1.36@73.442,103.187
  Bottom Layer w0.23: P2.9@58.928,94.488 60.985,94.488 v1(68.428,101.93) ; P2.9@59.214,94.202 cw(c59.906,93.51) 59.906,94.488 cw(c59.906,95.466) P2.9@59.214,94.774 ; P2.9@59.377,94.039 cw(c60.461,92.955) 60.461,94.488 cw(c60.461,96.021) P2.9@59.377,94.937 ; v1@68.043,101.93 cw(c67.113,101.93) 67.77,101.273 cw(c68.428,100.616) v1@68.428,101.545
NetP2_11: P2.11 U1.35 | length 25.2
  Top Layer w0.23: v1(72.746,104.648) 72.942,104.452 U1.35@72.942,103.187
  Bottom Layer w0.23: P2.11@58.928,97.028 62.789,97.028 67.285,101.524 67.285,103.657 68.275,104.648 v1(72.746,104.648) ; P2.11@59.214,96.742 cw(c59.906,96.05) 59.906,97.028 cw(c59.906,98.006) P2.11@59.214,97.314 ; P2.11@59.377,96.579 cw(c60.461,95.495) 60.461,97.028 cw(c60.461,98.561) P2.11@59.377,97.477 ; v1@72.473,104.376 ccw(c71.816,103.719) 71.816,104.648 ccw(c71.816,105.577) v1@72.473,104.92
NetP2_13: P2.13 U1.34 | length 20.3
  Top Layer w0.23: P2.13@58.928,99.568 62.173,102.813 70.858,102.813 71.574,102.097 72.136,102.097 72.442,102.403 U1.34@72.442,103.187 ; P2.13@58.928,99.973 ccw(c58.928,100.951) 59.619,100.259 ccw(c60.311,99.568) P2.13@59.333,99.568 ; P2.13@58.928,100.203 ccw(c58.928,101.736) 60.012,100.652 ccw(c61.096,99.568) P2.13@59.563,99.568 ; 72.33,102.291 ccw(c72.084,102.537) U1.34@72.432,102.537
NetP2_15: P2.15 U1.32 | length 16.4
  Top Layer w0.23: P2.15@58.928,102.108 61.782,104.962 U1.32@70.167,104.962 ; P2.15@58.928,102.513 ccw(c58.928,103.491) 59.619,102.799 ccw(c60.311,102.108) P2.15@59.333,102.108 ; P2.15@58.928,102.743 ccw(c58.928,104.276) 60.012,103.192 ccw(c61.096,102.108) P2.15@59.563,102.108
NetP2_17: P2.17 U1.31 | length 11.6
  Top Layer w0.23: P2.17@58.928,104.648 59.742,105.462 U1.31@70.167,105.462
NetP2_19: P2.19 U1.30 | length 15.7
  Top Layer w0.23: P2.19@58.928,106.553 cw(c58.928,105.02) 60.012,106.104 cw(c61.096,107.188) P2.19@59.563,107.188 ; P2.19@58.928,106.783 cw(c58.928,105.805) 59.619,106.497 cw(c60.311,107.188) P2.19@59.333,107.188 ; P2.19@58.928,107.188 60.154,105.962 U1.30@70.167,105.962
NetP2_21: P2.21 U1.29 | length 16.5
  Top Layer w0.23: P2.21@58.928,109.093 cw(c58.928,107.56) 60.012,108.644 cw(c61.096,109.728) P2.21@59.563,109.728 ; P2.21@58.928,109.323 cw(c58.928,108.345) 59.619,109.037 cw(c60.311,109.728) P2.21@59.333,109.728 ; P2.21@58.928,109.728 62.194,106.462 U1.29@70.167,106.462
NetP2_23: P2.23 U1.28 | length 17.4
  Top Layer w0.23: P2.23@58.928,111.633 cw(c58.928,110.1) 60.012,111.184 cw(c61.096,112.268) P2.23@59.563,112.268 ; P2.23@58.928,111.863 cw(c58.928,110.885) 59.619,111.577 cw(c60.311,112.268) P2.23@59.333,112.268 ; P2.23@58.928,112.268 64.234,106.962 U1.28@70.167,106.962
NetP2_25: P2.25 U1.27 | length 18.2
  Top Layer w0.23: P2.25@58.928,114.173 cw(c58.928,112.64) 60.012,113.724 cw(c61.096,114.808) P2.25@59.563,114.808 ; P2.25@58.928,114.403 cw(c58.928,113.425) 59.619,114.117 cw(c60.311,114.808) P2.25@59.333,114.808 ; P2.25@58.928,114.808 66.274,107.462 U1.27@70.167,107.462
NetP2_27: P2.27 U1.22 | length 14.3
  Top Layer w0.23: P2.27@58.928,117.348 59.763,117.348 66.998,110.113 68.555,110.113 68.707,109.962 U1.22@70.167,109.962
NetP2_29: P2.29 U1.21 | length 25
  Top Layer w0.23: P2.29@58.643,119.888 ccw(c59.913,119.888) 59.015,118.99 ; P2.29@58.873,119.888 ccw(c60.698,119.888) 59.408,118.597 ; P2.29@58.928,119.888 58.928,119.077 67.461,110.543 68.985,110.543 69.067,110.462 U1.21@70.167,110.462 ; P2.29@59.103,119.888 ccw(c61.484,119.888) 59.8,118.205 ; P2.29@59.333,119.888 ccw(c62.269,119.888) 60.193,117.812 ; P2.29@59.563,119.888 ccw(c63.054,119.888) 60.586,117.419
NetP2_31: P2.31 U1.20 | length 22.1
  Top Layer w0.23: P2.31@58.928,122.428 60.547,122.428 66.116,116.859 66.116,113.185 68.275,111.026 68.411,111.026 68.463,110.973 69.415,110.974 69.415,110.962 U1.20@70.167,110.962 ; P2.31@59.214,122.142 cw(c59.906,121.45) 59.906,122.428 cw(c59.906,123.406) P2.31@59.214,122.714 ; P2.31@59.377,121.979 cw(c60.461,120.895) 60.461,122.428 cw(c60.461,123.961) P2.31@59.377,122.877
NetP2_33: P2.33 U1.19 | length 23.1
  Top Layer w0.23: P2.33@58.928,124.333 cw(c58.928,122.8) 60.012,123.884 cw(c61.096,124.968) P2.33@59.563,124.968 ; P2.33@58.928,124.563 cw(c58.928,123.585) 59.619,124.277 cw(c60.311,124.968) P2.33@59.333,124.968 ; P2.33@58.928,124.968 68.456,115.44 68.456,111.506 68.5,111.462 U1.19@70.167,111.462
NetP2_35: P2.35 U1.9 | length 45.4
  Top Layer w0.23: 74.872,129.909 cw(c77.127,129.909) v1@75.532,131.503 ; 74.872,130.464 cw(c76.572,130.464) v1@75.37,131.666 ; 74.872,131.019 cw(c76.016,131.019) v1@75.207,131.828 ; v1(75.26,131.775) 74.872,131.387 74.872,115.759 75.442,115.189 U1.9@75.442,114.237
  Bottom Layer w0.23: P2.35@58.928,127.508 61.874,127.508 66.142,131.775 v1(75.26,131.775) ; P2.35@59.214,127.222 cw(c59.906,126.53) 59.906,127.508 cw(c59.906,128.486) P2.35@59.214,127.794 ; P2.35@59.377,127.059 cw(c60.461,125.975) 60.461,127.508 cw(c60.461,129.041) P2.35@59.377,127.957 ; v1@74.988,131.503 ccw(c74.331,130.846) 74.331,131.775 ccw(c74.331,132.705) v1@74.988,132.047
NetP2_37: P2.37 U1.10 | length 53.1
  Top Layer w0.23: v1(74.752,112.573) 74.942,112.763 U1.10@74.942,114.237
  Bottom Layer w0.23: P2.37@58.293,130.048 cw(c56.76,130.048) 57.844,128.964 cw(c58.928,127.88) P2.37@58.928,129.413 ; P2.37@58.523,130.048 cw(c57.545,130.048) 58.237,129.357 cw(c58.928,128.665) P2.37@58.928,129.643 ; P2.37@58.928,130.048 57.836,128.956 55.27,128.956 54.051,127.737 54.051,112.166 55.016,111.201 59.893,111.201 64.694,116.002 71.323,116.002 v1(74.752,112.573) ; v1@74.367,112.573 ccw(c73.438,112.573) 74.095,113.23 ccw(c74.752,113.887) v1@74.752,112.958
NetP2_39: P2.39 R8.2 U1.13 | length 66.7
  Top Layer w0.23: v1@71.984,132.99 cw(c71.984,132.061) 72.641,132.718 cw(c73.298,133.375) v1@72.369,133.375 ; v1(71.984,133.375) 73.442,131.917 U1.13@73.442,114.237 73.442,112.075 v1(73.101,111.735) ; v1@72.829,112.007 ccw(c71.349,113.487) U1.13@73.442,113.487 ; v1@72.992,111.844 ccw(c71.904,112.932) 73.442,112.932 ; v1@73.154,111.682 ccw(c72.459,112.376) 73.442,112.376
  Bottom Layer w0.23: P2.39@58.928,132.588 59.715,133.375 v1(71.984,133.375) ; R8.2@68.834,96.901 70.279,98.346 73.073,98.346 74.447,99.72 74.447,106.297 74.014,106.731 74.014,110.822 v1(73.101,111.735) ; R8.2@68.834,97.256 ccw(c68.834,98.113) 69.44,97.507 ccw(c70.046,96.901) R8.2@69.189,96.901 ; R8.2@68.834,97.486 ccw(c68.834,98.898) 69.833,97.9 ccw(c70.831,96.901) R8.2@69.419,96.901 ; v1@71.711,133.103 ccw(c71.054,132.446) 71.054,133.375 ccw(c71.054,134.305) v1@71.711,133.648 ; v1@73.101,111.35 cw(c73.101,110.42) 73.758,111.077 cw(c74.416,111.735) v1@73.486,111.735
NetP6_3: P6.3 R6.2 | length 15
  Top Layer w0.23: P6.3@84.836,140.081 cw(c84.836,138.548) 85.92,139.632 cw(c87.004,140.716) P6.3@85.471,140.716 ; P6.3@84.836,140.311 cw(c84.836,139.333) 85.527,140.025 cw(c86.219,140.716) P6.3@85.241,140.716 ; P6.3@84.836,140.716 86.106,139.446 86.106,136.652 R6.2@88.138,134.62 ; R6.2@87.553,134.62 ccw(c86.141,134.62) 87.139,135.619 ccw(c88.138,136.617) R6.2@88.138,135.205 ; R6.2@87.783,134.62 ccw(c86.926,134.62) 87.532,135.226 ccw(c88.138,135.832) R6.2@88.138,134.975
NetP7_2: P7.2 P_S.3 | length 9.7
  Bottom Layer w0.23: P7.2@96.52,82.804 99.06,85.344 ; P7.2@96.52,83.209 ccw(c96.52,84.187) 97.211,83.495 ccw(c97.903,82.804) P7.2@96.925,82.804 ; P7.2@96.52,83.439 ccw(c96.52,84.972) 97.604,83.888 ccw(c98.688,82.804) P7.2@97.155,82.804 ; P_S.3@99.505,85.066 ccw(c99.06,84.849) 99.06,85.344 ; P_S.3@99.505,85.622 cw(c99.06,85.839) 99.06,85.344 ; P_S.3@100.076,85.344 99.06,85.344
NRST: P6.15 R2.1 S1.2 U1.39 | length 172.2
  Top Layer w0.23: U1.39@74.942,103.187 74.942,104.504 75.797,105.359 v1(76.987,105.359) ; v1@76.715,105.087 ccw(c76.058,104.43) 76.058,105.359 ccw(c76.058,106.289) v1@76.715,105.631 ; S1.2@109.428,97.598 ccw(c107.926,97.715) 108.991,98.781 ; S1.2@109.658,97.581 ccw(c108.582,97.664) 109.345,98.427 ccw(c110.108,99.19) S1.2@110.191,98.114 ; S1.2@110.174,98.344 cw(c110.057,99.846) 108.991,98.781 ; S1.2@110.236,97.536 108.991,98.781 ; v1@111.031,138.005 cw(c110.373,137.348) 111.303,137.348 cw(c112.232,137.348) v1@111.575,138.005 ; v1(111.303,138.278) 111.303,119.939 108.991,117.627 108.991,98.781
  Bottom Layer w0.23: P6.15@69.596,140.716 71.247,142.367 107.213,142.367 v1(111.303,138.278) ; P6.15@69.596,141.121 ccw(c69.596,142.099) 70.287,141.407 ccw(c70.979,140.716) P6.15@70.001,140.716 ; P6.15@69.596,141.351 ccw(c69.596,142.884) 70.68,141.8 ccw(c71.764,140.716) P6.15@70.231,140.716 ; v1(76.987,105.359) 78.08,106.451 79.654,106.451 82.906,103.2 82.906,99.441 83.718,98.628 92.659,98.628 93.98,99.949 93.98,102.616 93.48,103.116 ; v1@76.987,105.744 ccw(c76.987,106.674) 77.645,106.016 ccw(c78.302,105.359) v1@77.372,105.359 ; R2.1@86.36,101.346 88.13,103.116 ; R2.1@86.36,101.701 ccw(c86.36,102.558) 86.966,101.952 ccw(c87.572,101.346) R2.1@86.715,101.346 ; R2.1@86.36,101.931 ccw(c86.36,103.343) 87.359,102.345 ccw(c88.357,101.346) R2.1@86.945,101.346 ; S1.2@109.426,97.536 ccw(c107.47,97.536) 108.853,98.919 ccw(c110.236,100.302) S1.2@110.236,98.346 ; S1.2@109.656,97.536 ccw(c108.256,97.536) 109.246,98.526 ccw(c110.236,99.516) S1.2@110.236,98.116 ; S1.2@110.236,97.536 104.656,103.116 93.48,103.116 ; v1@110.918,138.278 ccw(c109.988,138.278) 110.646,138.935 ccw(c111.303,139.592) v1@111.303,138.663 ; 88.13,103.116 93.48,103.116 ; 88.13,103.116 93.48,103.116
PLLRC: C8.1 R1.1 U1.63 | length 44.9
  Top Layer w0.23: U1.63@81.217,111.962 v1(85.09,111.962) ; v1@84.818,111.69 ccw(c84.161,111.033) 84.161,111.962 ccw(c84.161,112.891) v1@84.818,112.234 ; R1.1@92.125,127.508 cw(c90.713,127.508) 91.711,126.509 cw(c92.71,125.511) R1.1@92.71,126.923 ; R1.1@92.355,127.508 cw(c91.498,127.508) 92.104,126.902 cw(c92.71,126.296) R1.1@92.71,127.153 ; R1.1@92.71,127.508 91.592,126.39 91.592,122.479 93.98,120.091 C8.1@93.98,117.602 ; C8.1@93.478,118.104 ccw(c92.266,119.316) 93.98,119.316 ccw(c95.694,119.316) C8.1@94.482,118.104 ; C8.1@93.641,117.941 ccw(c92.821,118.761) 93.98,118.761 ccw(c95.139,118.761) C8.1@94.319,117.941
  Bottom Layer w0.23: v1@84.818,112.234 ccw(c84.161,112.891) 85.09,112.891 ccw(c86.019,112.891) v1@85.362,112.234 ; v1(85.09,111.962) 85.09,116.078 87.757,118.745 92.837,118.745 ; C8.1@93.271,117.632 ccw(c91.787,117.695) 92.837,118.745 ; C8.1@93.5,117.622 ccw(c92.497,117.665) 93.207,118.375 ccw(c93.917,119.085) C8.1@93.96,118.082 ; C8.1@93.95,118.311 cw(c93.887,119.795) 92.837,118.745 ; C8.1@93.98,117.602 92.837,118.745
TCK: P6.9 P6.11 R11.2 U1.53 | length 108.8
  Top Layer w0.23: v1@77.214,107.262 ccw(c77.938,107.986) 77.938,106.962 ; P6.9@77.216,140.716 78.804,142.304 83.502,142.304 83.566,142.24 83.566,136.525 86.995,133.096 86.995,124.892 92.837,119.05 92.837,102.591 v1(93.142,102.286) ; P6.9@77.216,141.121 ccw(c77.216,142.099) 77.907,141.407 ccw(c78.599,140.716) P6.9@77.621,140.716 ; P6.9@77.216,141.351 ccw(c77.216,142.884) 78.3,141.8 ccw(c79.384,140.716) P6.9@77.851,140.716 ; v1(77.267,107.315) 77.62,106.962 U1.53@81.217,106.962 ; v1@77.376,107.425 ccw(c78.493,108.541) 78.493,106.962 ; v1@77.539,107.587 ccw(c79.049,109.097) 79.049,106.962 ; 92.837,102.841 ccw(c93.697,102.841) v1@93.089,102.233 ; 92.837,103.396 ccw(c94.252,103.396) v1@93.251,102.395 ; 92.837,103.951 ccw(c94.807,103.951) v1@93.414,102.558
  Bottom Layer w0.23: P6.11@74.676,140.716 P6.9@77.216,140.716 ; P6.11@74.962,140.43 cw(c75.654,139.738) 75.654,140.716 cw(c75.654,141.694) P6.11@74.962,141.002 ; P6.11@75.125,140.267 cw(c76.209,139.183) 76.209,140.716 cw(c76.209,142.249) P6.11@75.125,141.165 ; P6.9@76.767,140.267 ccw(c75.683,139.183) 75.683,140.716 ccw(c75.683,142.249) P6.9@76.767,141.165 ; P6.9@76.93,140.43 ccw(c76.238,139.738) 76.238,140.716 ccw(c76.238,141.694) P6.9@76.93,141.002 ; v1(77.267,107.315) 79.705,107.315 83.718,103.302 83.718,100.152 84.531,99.339 87.401,99.339 R11.2@89.408,101.346 92.202,101.346 v1(93.142,102.286) ; v1@77.539,107.043 cw(c78.196,106.386) 78.196,107.315 cw(c78.196,108.244) v1@77.539,107.587 ; R11.2@88.823,101.346 cw(c87.411,101.346) 88.409,100.347 cw(c89.408,99.349) R11.2@89.408,100.761 ; R11.2@89.053,101.346 cw(c88.196,101.346) 88.802,100.74 cw(c89.408,100.134) R11.2@89.408,100.991 ; R11.2@89.659,101.095 cw(c90.265,100.489) 90.265,101.346 cw(c90.265,102.203) R11.2@89.659,101.597 ; R11.2@89.822,100.932 cw(c90.82,99.934) 90.82,101.346 cw(c90.82,102.758) R11.2@89.822,101.76 ; v1@92.757,102.286 cw(c91.827,102.286) 92.485,101.629 cw(c93.142,100.971) v1@93.142,101.901
TDI: P6.5 R7.2 U1.33 | length 100.5
  Top Layer w0.23: v1@70.391,115.436 ccw(c69.733,116.093) 70.663,116.093 ccw(c71.592,116.093) v1@70.935,115.436 ; R7.2@70.452,134.206 cw(c69.454,133.208) 70.866,133.208 cw(c72.278,133.208) R7.2@71.28,134.206 ; R7.2@70.615,134.369 cw(c70.009,133.763) 70.866,133.763 cw(c71.723,133.763) R7.2@71.117,134.369 ; v1(70.663,115.164) 70.663,128.092 70.866,128.295 R7.2@70.866,134.62 ; v1@71.658,105.784 cw(c71.001,105.127) 71.931,105.127 cw(c72.86,105.127) v1@72.203,105.784 ; v1(71.931,106.056) 71.931,103.833 71.942,103.833 U1.33@71.942,103.187
  Bottom Layer w0.23: v1@70.391,114.891 cw(c69.733,114.234) 70.663,114.234 cw(c71.592,114.234) v1@70.935,114.891 ; R7.2@70.452,134.206 ccw(c69.454,133.208) 69.454,134.62 ccw(c69.454,136.032) R7.2@70.452,135.034 ; R7.2@70.615,134.369 ccw(c70.009,133.763) 70.009,134.62 ccw(c70.009,135.477) R7.2@70.615,134.871 ; v1(70.663,115.164) 70.663,107.324 v1(71.931,106.056) ; R7.2@70.866,134.62 59.08,134.62 57.861,133.401 57.861,131.928 57.455,131.521 55.88,131.521 55.321,132.08 55.321,137.465 57.506,139.649 81.229,139.649 ; v1@71.546,106.056 ccw(c70.616,106.056) 71.273,106.714 ccw(c71.931,107.371) v1@71.931,106.441 ; P6.5@81.661,140.709 cw(c80.187,140.692) 81.229,139.649 ; P6.5@81.891,140.711 cw(c80.951,140.701) 81.616,140.036 cw(c82.281,139.371) P6.5@82.291,140.311 ; P6.5@82.289,140.081 ccw(c82.272,138.607) 81.229,139.649 ; P6.5@82.296,140.716 81.229,139.649
TDO: P6.13 U1.49 | length 90.7
  Top Layer w0.23: U1.49@81.217,104.962 82.347,104.962 v1(85.344,107.959) ; v1@84.959,107.959 cw(c84.03,107.959) 84.687,107.302 cw(c85.344,106.645) v1@85.344,107.574
  Bottom Layer w0.23: P6.13@72.136,140.716 73.355,141.935 98.984,141.935 106.985,133.934 106.985,127.178 96.139,116.332 87.782,116.332 86.868,115.418 86.868,111.354 85.344,109.83 v1(85.344,107.959) ; P6.13@72.136,141.121 ccw(c72.136,142.099) 72.827,141.407 ccw(c73.519,140.716) P6.13@72.541,140.716 ; P6.13@72.136,141.351 ccw(c72.136,142.884) 73.22,141.8 ccw(c74.304,140.716) P6.13@72.771,140.716 ; v1@85.072,108.231 ccw(c84.415,108.889) 85.344,108.889 ccw(c86.273,108.889) v1@85.616,108.231
TMS: P6.7 R10.2 U1.51 | length 60.2
  Top Layer w0.23: v1@75.344,108.618 cw(c74.686,107.96) 75.616,107.96 cw(c76.545,107.96) v1@75.888,108.618 ; v1(75.616,108.89) 75.616,107.336 76.452,106.5 79.896,106.5 80.434,105.962 U1.51@81.217,105.962 ; P6.7@79.756,140.081 cw(c79.756,138.548) 80.84,139.632 cw(c81.924,140.716) P6.7@80.391,140.716 ; P6.7@79.756,140.311 cw(c79.756,139.333) 80.447,140.025 cw(c81.139,140.716) P6.7@80.161,140.716 ; P6.7@79.756,140.716 81.026,139.446 81.026,136.398 83.312,134.112 83.312,120.65 R10.2@82.296,119.634 ; 80.322,106.073 ccw(c80.567,106.318) U1.51@80.567,105.972 ; R10.2@82.296,119.989 ccw(c82.296,120.846) 82.902,120.24 ccw(c83.508,119.634) R10.2@82.651,119.634 ; R10.2@82.296,120.219 ccw(c82.296,121.631) 83.295,120.633 ccw(c84.293,119.634) R10.2@82.881,119.634
  Bottom Layer w0.23: v1@75.541,108.89 cw(c76.341,108.89) 75.775,109.456 ; v1(75.616,108.89) 75.616,109.296 82.296,115.976 R10.2@82.296,119.634 ; v1@75.771,108.89 cw(c77.126,108.89) 76.168,109.848 ; v1@76.001,108.89 cw(c77.911,108.89) 76.56,110.241 ; R10.2@81.882,119.22 cw(c80.884,118.222) 82.296,118.222 cw(c83.708,118.222) R10.2@82.71,119.22 ; R10.2@82.045,119.383 cw(c81.439,118.777) 82.296,118.777 cw(c83.153,118.777) R10.2@82.547,119.383
TST: P3.2 U1.40 | length 51.4
  Top Layer w0.23: U1.40@75.442,103.187 75.442,104.119 75.844,104.521 79.449,104.521 80.523,103.447 80.523,98.414 80.061,97.952 79.435,97.952 76.581,95.098 76.581,79.248 77.089,78.74 86.411,78.74 86.919,79.248 86.919,81.737 ; P3.2@85.852,82.804 86.919,81.737 ; P3.2@85.857,82.399 cw(c85.867,81.459) 86.532,82.124 cw(c87.197,82.789) P3.2@86.257,82.799 ; P3.2@85.859,82.169 cw(c85.876,80.695) 86.919,81.737 ; P3.2@86.487,82.797 ccw(c87.961,82.78) 86.919,81.737
VDDCORE: C5.1 C10.2 U1.8 U1.12 U1.24 U1.54 U1.64 | length 81.1
  Top Layer w0.23: U1.24@70.167,108.962 72.579,108.962 72.764,108.777 73.674,108.777 74.168,109.272 74.168,109.724 73.937,109.955 73.937,112.166 ; U1.12@73.942,114.237 73.942,113.591 U1.12@73.937,113.586 ; U1.8@75.942,114.237 75.942,112.317 ; C5.1@77.724,94.472 88.341,105.089 88.341,109.601 90.043,111.303 90.043,116.459 ; C5.1@77.724,94.752 ccw(c77.724,95.428) 78.202,94.95 ccw(c78.68,94.472) C5.1@78.004,94.472 ; C5.1@77.724,94.982 ccw(c77.724,96.213) 78.595,95.343 ccw(c79.465,94.472) C5.1@78.234,94.472 ; U1.54@81.217,107.462 78.614,107.462 76.223,109.853 75.184,109.853 74.775,110.261 74.775,111.15 75.372,111.747 ; C10.2@88.19,117.602 cw(c86.476,117.602) 87.688,116.39 cw(c88.9,115.178) C10.2@88.9,116.892 ; C10.2@88.42,117.602 cw(c87.261,117.602) 88.081,116.783 cw(c88.9,115.963) C10.2@88.9,117.122 ; C10.2@88.92,117.122 cw(c88.963,116.119) 89.673,116.829 cw(c90.383,117.539) C10.2@89.38,117.582 ; C10.2@88.93,116.893 cw(c88.993,115.409) 90.043,116.459 ; C10.2@89.609,117.572 ccw(c91.093,117.509) 90.043,116.459 ; 73.937,112.166 74.356,111.747 75.372,111.747 ; 73.937,112.166 U1.12@73.937,113.586 ; 73.937,112.166 U1.12@73.937,113.586 ; 75.372,111.747 75.942,112.317 ; 75.372,111.747 75.942,112.317 ; 75.942,112.317 76.403,111.887 77.812,111.887 78.387,112.462 U1.64@81.217,112.462 83.76,112.462 C10.2@88.9,117.602 90.043,116.459
XIN: C3.1 U1.62 Y1.1 | length 44.2
  Top Layer w0.23: v1(79.248,111.557) 79.343,111.462 U1.62@81.217,111.462 ; v1@79.358,111.666 ccw(c79.851,112.16) 79.851,111.462 ; v1@79.52,111.285 cw(c79.949,110.856) 79.949,111.462 ; v1@79.52,111.829 ccw(c80.406,112.715) 80.406,111.462
  Bottom Layer w0.23: Y1.1@71.628,124.486 73.126,125.984 C3.1@76.454,125.984 78.689,123.749 82.296,123.749 83.312,122.733 83.312,115.621 v1(79.248,111.557) ; Y1.1@71.628,124.791 ccw(c71.628,125.527) 72.149,125.007 ccw(c72.669,124.486) Y1.1@71.933,124.486 ; Y1.1@71.628,125.021 ccw(c71.628,126.313) 72.541,125.399 ccw(c73.455,124.486) Y1.1@72.163,124.486 ; C3.1@75.952,125.482 ccw(c74.74,124.27) 74.74,125.984 ccw(c74.74,127.698) C3.1@75.952,126.486 ; C3.1@76.115,125.645 ccw(c75.295,124.825) 75.295,125.984 ccw(c75.295,127.143) C3.1@76.115,126.323 ; C3.1@76.454,125.274 cw(c76.454,123.56) 77.666,124.772 cw(c78.878,125.984) C3.1@77.164,125.984 ; C3.1@76.454,125.504 cw(c76.454,124.345) 77.273,125.165 cw(c78.093,125.984) C3.1@76.934,125.984 ; v1@79.248,111.942 ccw(c79.248,112.871) 79.905,112.214 ccw(c80.562,111.557) v1@79.633,111.557
XOUT: C6.1 U1.61 Y1.2 | length 39.6
  Top Layer w0.23: v1(75.59,110.719) 79.741,110.719 79.985,110.962 U1.61@81.217,110.962 ; v1@75.863,110.446 cw(c76.52,109.789) 76.52,110.719 cw(c76.52,111.648) v1@75.863,110.991
  Bottom Layer w0.23: Y1.2@71.628,121.386 74.016,121.386 74.042,121.412 C6.1@76.454,121.412 79.375,118.491 79.375,113.792 77.317,111.735 76.606,111.735 v1(75.59,110.719) ; Y1.2@71.844,121.17 cw(c72.364,120.65) 72.364,121.386 cw(c72.364,122.122) Y1.2@71.844,121.602 ; Y1.2@72.006,121.008 cw(c72.92,120.094) 72.92,121.386 cw(c72.92,122.678) Y1.2@72.006,121.764 ; v1@75.59,111.104 ccw(c75.59,112.033) 76.248,111.376 ccw(c76.905,110.719) v1@75.975,110.719 ; C6.1@75.952,120.91 ccw(c74.74,119.698) 74.74,121.412 ccw(c74.74,123.126) C6.1@75.952,121.914 ; C6.1@76.115,121.073 ccw(c75.295,120.253) 75.295,121.412 ccw(c75.295,122.571) C6.1@76.115,121.751 ; C6.1@76.454,120.702 cw(c76.454,118.988) 77.666,120.2 cw(c78.878,121.412) C6.1@77.164,121.412 ; C6.1@76.454,120.932 cw(c76.454,119.773) 77.273,120.593 cw(c78.093,121.412) C6.1@76.934,121.412
pads on no net: J1.5 J1.6 P1.1 P2.20 P3.3 P4.3 P5.3 P6.17 P6.19 P7.1

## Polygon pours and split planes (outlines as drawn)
GND on Top Layer "Top Overlay-No Net" (solid): 52.1,144.9 52.1,77.5 119.5,77.5 119.5,144.9
GND on Bottom Layer "Top Overlay-No Net" (solid): 52.1,144.9 52.1,77.5 119.5,77.5 119.5,144.9

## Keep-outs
Keep-Out Layer:
  rectangle: 115.854,77.604 119.634,81.407
  rectangle: 115.727,141.104 119.507,144.907
  rectangle: 51.973,141.224 55.753,145.027
  rectangle: 51.973,77.604 55.753,81.407
  lines w0.3: 52.1,77.5 52.1,144.9 119.5,144.9 119.5,77.5 52.1,77.5

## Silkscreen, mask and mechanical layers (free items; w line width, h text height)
Top Overlay:
  text "SalehJG" at 104.902,92.71 h1.52
  text "Sam7s" at 110.744,90.424 h1.52
Drill Drawing:
  text ".LEGEND" at 125.88,81.28 h1.52
  text "Drill Drawing." at 125.88,78.74 h1.52

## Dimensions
52.1,77.5 to 52.1,144.9 on Mechanical 1
52.1,77.5 to 119.5,77.5 on Mechanical 1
